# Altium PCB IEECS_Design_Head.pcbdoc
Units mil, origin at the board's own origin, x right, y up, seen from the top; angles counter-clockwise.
Board outline 1106.03 x 1212.03 mil, 2 copper layers (Top Layer, Bottom Layer); 10 components, 10 nets, 22 pads, 16 vias.
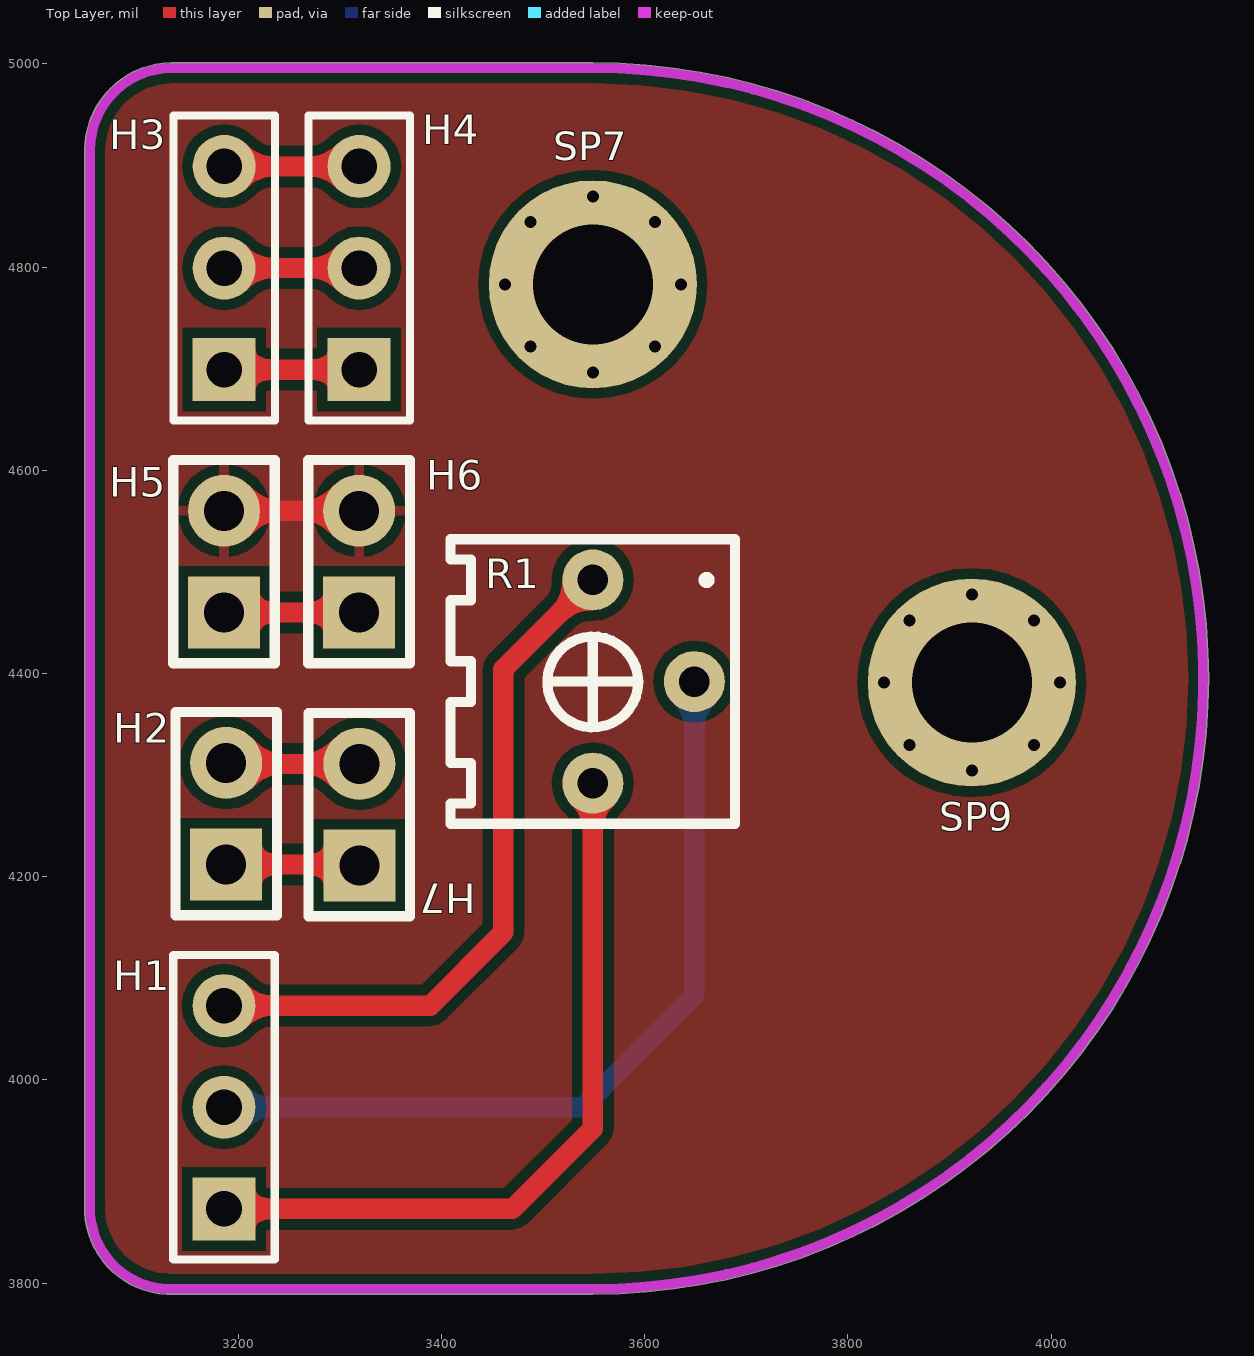
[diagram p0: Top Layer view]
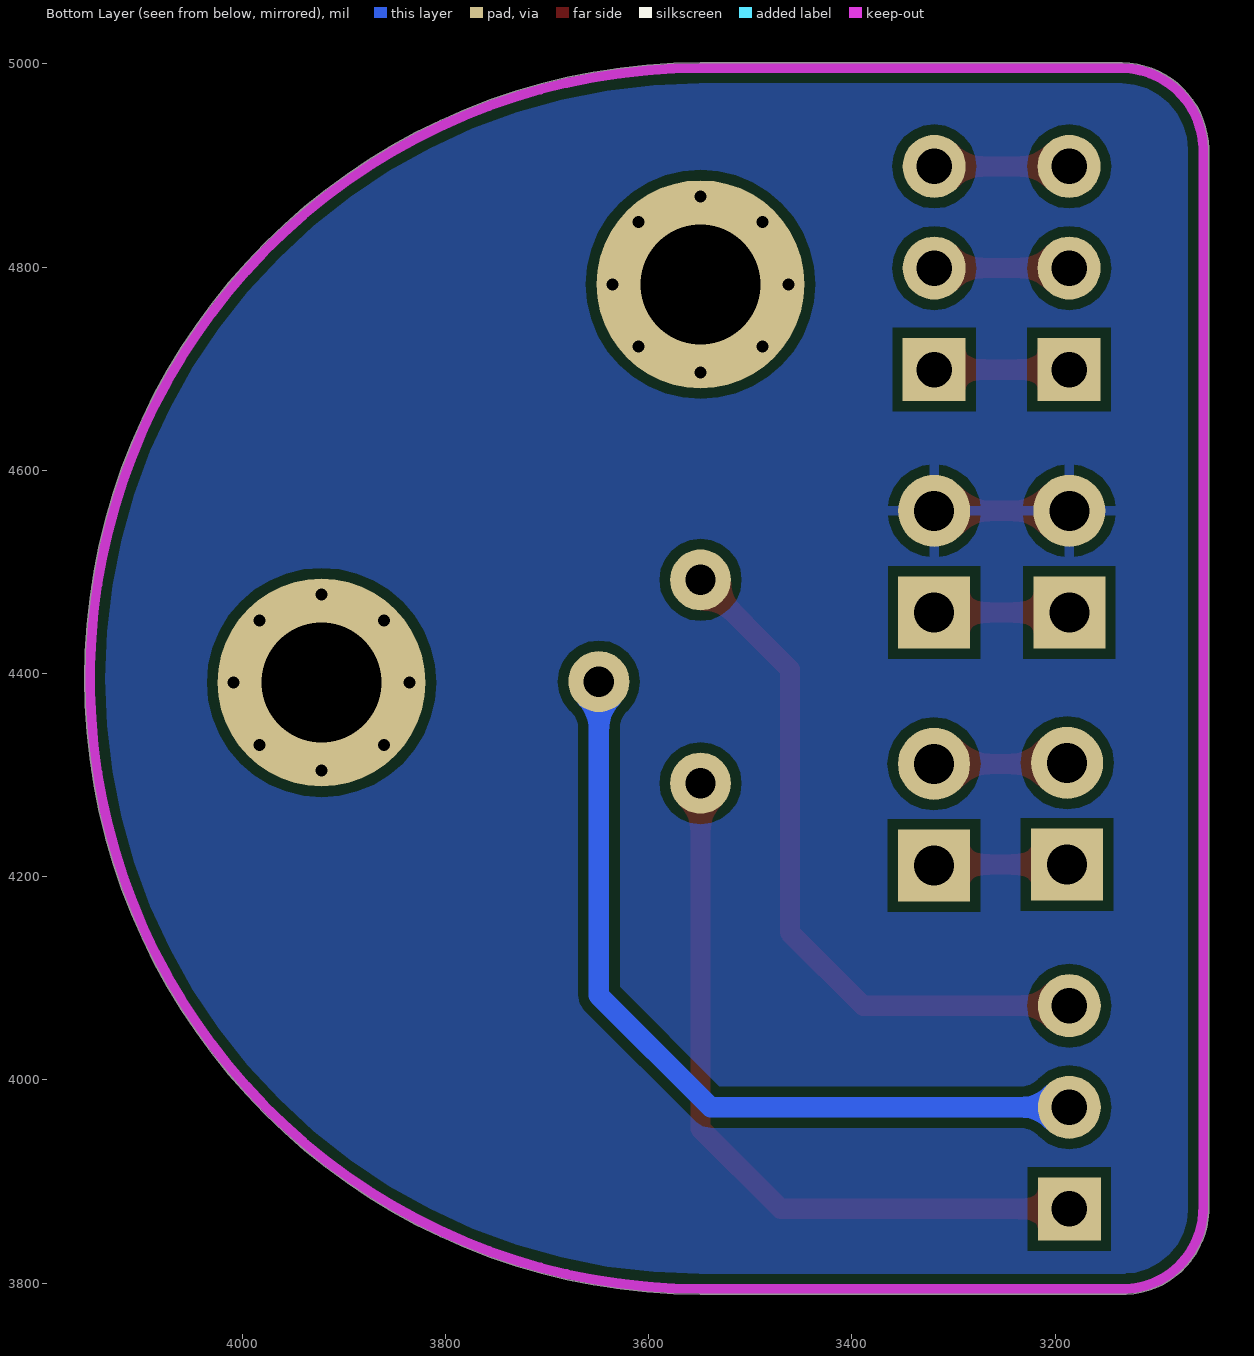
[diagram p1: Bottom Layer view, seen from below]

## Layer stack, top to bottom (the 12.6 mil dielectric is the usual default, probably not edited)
Top Solder: solder mask 0.4, Solder Resist, Dk 3.5
Top Layer: signal copper 1.4
Dielectric 1: dielectric 12.6, FR-4, Dk 4.8
Bottom Layer: signal copper 1.4
Bottom Solder: solder mask 0.4, Solder Resist, Dk 3.5

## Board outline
3129.78,3788.99 cw(c3133.5,3873.5) 3048.99,3877.11 3048.99,4916 cw(c3054,4916) 3048.99,4916.32 3049,4916.32 cw(c3135,4915) 3133.69,5001.01 cw(c3134,4996) 3134,5001.02 3549,5001.02 cw(c3549,4395) 4155.02,4395 cw(c3549,4395) 3549,3788.99 3130,3788.99 cw(c3130,3794)

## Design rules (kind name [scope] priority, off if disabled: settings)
Clearance [All] p1: gap=10 ignorepadtopadclearanceinfootprint=FALSE except(0: Arc-Hole Track-Hole SMDPad-Hole THPad-Hole Via-Hole Fill-Hole Poly-Hole Region-Hole Text-Hole)
PolygonConnect [All] p1: connectstyle=Relief reliefconductorwidth=10 reliefentries=4 polygonreliefangle="90 Angle" airgapwidth=10
RoutingVias [All] p1: holewidth=28 width=50 viastyle="Through Hole" minholewidth=28 minwidth=50 maxholewidth=28 maxwidth=50
SolderMaskExpansion [All] p1: expansion=4
Width [All] p1: maxlimit=20 minlimit=10 preferedwidth=10 minimp=50.000000 maximp=50.000000 favimp=50.000000
30 further rules are at their usual default settings.

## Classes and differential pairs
component class IEECS_Design_Head: H1 H2 H3 H4 H5 H6 R1

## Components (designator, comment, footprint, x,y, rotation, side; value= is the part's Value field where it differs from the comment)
H1 "HDR-M_2.54_1x3P" Pin1X3 3188.14,3971 r0 top
H2 "HDR-M_2.54_1x2P" Pin1x2 3184,4266 r270 top
H3 "HDR-M_2.54_1x3P" Pin1X3 3188.34,4797 r0 top
H4 "HDR-M_2.54_1x3P" Pin1X3 3321.14,4797 r0 top
H5 "HDR-M_2.54_1x2P" Pin1x2 3181.8,4514.07 r270 top
H6 "HDR-M_2.54_1x2P" Pin1x2 3314.8,4514.07 r270 top
H7 "HDR-M_2.54_1x2P" Pin1x2 3315,4265 r270 top (schematic designator H2)
R1 "5kΩ" Slide_Res 3550.5,4389.1 r0 top
SP7 "M3铜柱" M3-MountHole-Plated 3549,4783 r0 top (schematic designator SP2)
SP9 "M3铜柱" M3-MountHole-Plated 3922,4391 r0 top (schematic designator SP2)

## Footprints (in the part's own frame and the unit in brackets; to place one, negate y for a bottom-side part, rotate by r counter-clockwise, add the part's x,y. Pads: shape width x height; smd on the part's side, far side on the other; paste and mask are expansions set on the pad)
M3-MountHole-Plated [mm]
  round 5.2 hole 3: 1(0,0)
Pin1x2 [mm]
  rect 1.8x1.8 hole 1 mask+0.051: 1(1.373,0.107)
  round 1.8 hole 1 mask+0.051: 2(-1.167,0.107)
  silkscreen extent -2.44,-1.16 2.64,1.38, body extent -2.23,-1.07 2.43,1.25, height 7.82
Pin1X3 [mil]
  rect 62x62 hole 35: 1(-2.14,-98)
  round 62 hole 35: 2(-2.14,2) 3(-2.14,102)
  silkscreen extent -52,-148 48,152, body extent -52,-148 48,152, height 335
Slide_Res [mil]
  round 60 hole 30 mask+2: 1(-1.5,102.9) 2(98.5,2.9) 3(-1.5,-97.1)
  silkscreen extent -142,-137 138,143, body extent -143,-133 137,139, height 184

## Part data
R1: library part 3362P-1-502, "阻值:5kΩ;精度:±10%;温度系数:±250ppm/;"
SP7 SP9: library part 铜柱小焊盘, "铜柱"

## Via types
v1: diameter 23.62, hole 11.81, Top Layer to Bottom Layer, 16 vias

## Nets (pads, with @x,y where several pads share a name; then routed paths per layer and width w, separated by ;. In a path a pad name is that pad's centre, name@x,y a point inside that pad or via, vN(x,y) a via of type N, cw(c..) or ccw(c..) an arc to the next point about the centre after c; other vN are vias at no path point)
GND: H5.2 H6.2 | length 133
  Top Layer w20: H5.2 H6.2
LIGHT+: H5.1 H6.1 | length 133
  Top Layer w20: H5.1 H6.1
MOTOR+: H2.1 H7.1 | length 131.4
  Top Layer w20: H2.1 3318.2,4211.93 H7.1
MOTOR-: H2.2 H7.2 | length 131.4
  Top Layer w20: H2.2 3189.2,4310.93 H7.2
NECK_COMMON: H3.2 H4.2 | length 132.8
  Top Layer w20: H3.2 H4.2
NECK_LEFT: H3.1 H4.1 | length 132.8
  Top Layer w20: H3.1 H4.1
NECK_RIGHT: H3.3 H4.3 | length 132.8
  Top Layer w20: H3.3 H4.3
PHOTORESISTOR_COMMON: H1.2 R1.2 | length 817.6
  Bottom Layer w20: H1.2 3539,3973 3649,4083 R1.2
PHOTORESISTOR_LEFT: H1.1 R1.3 | length 735.7
  Top Layer w20: H1.1 3470,3873 3549,3952 R1.3
PHOTORESISTOR_RIGHT: H1.3 R1.1 | length 688.3
  Top Layer w20: H1.3 3389,4073 3461,4145 3461,4404 R1.1
pads on no net: SP7.1 SP9.1
copper on no net:
  other v1: 3922,4304.39 3860.75,4329.75 3983.25,4329.75 3835.39,4391 4008.61,4391 3860.75,4452.25 3983.25,4452.25 3922,4477.61 3549,4696.39 3487.75,4721.75 3610.25,4721.75 3462.39,4783 3635.61,4783 3487.75,4844.25 3610.25,4844.25 3549,4869.61

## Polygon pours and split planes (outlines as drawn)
GND on Top Layer (solid, remove dead copper, pour order 4): 2915,5060 2953,5022 4207,5022 4207,3721 4244,3684 2789,3684
GND on Bottom Layer (solid, remove dead copper, pour order 6): 2866,5063 4190,5063 4207,5080 4336,4951 4336,3925 4073,3662 2759,3662

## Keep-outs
Keep-Out Layer:
  lines w10: 3054,4915 cw(c3135,4915) 3135,4996 ; 3054,4916 3054,4394 3054,3877 ccw(c3133.5,3873.5) 3130,3794 3549,3794 ccw(c3549,4395) 3549,4996 3134,4996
